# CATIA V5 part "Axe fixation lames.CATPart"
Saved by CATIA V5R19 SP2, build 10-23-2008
Part number: Axe fixation lames
Bounding box of the stored display mesh (mm): x 0 to 24, y -6 to 6, z -6 to 6
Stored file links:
  C:\Users\Romain\Documents\IFMA\2A\cours\S3\Projet CFAO-IAO\CFAO\Catia\Organe de fixation\Axe fixation lames.CATPart
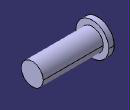
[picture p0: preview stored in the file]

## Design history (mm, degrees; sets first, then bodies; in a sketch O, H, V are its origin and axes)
Body1 (main body)
  Sketch1 on yz-plane, origin (0, 0, 0), H (0, 1, 0), V (0, 0, 1)
    circle A1 centre (0, 0) radius 6
    radius A1 = 6
  Pad1: profile Sketch1, direction (1, 0, 0), length 2
  Sketch2 on end face of Pad1, origin (2, 0, 0), H (0, 1, 0), V (0, 0, 1)
    circle A1 centre (0, 0) radius 4
    radius A1 = 4
  Pad2: profile Sketch2, direction (1, 0, 0), length 22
